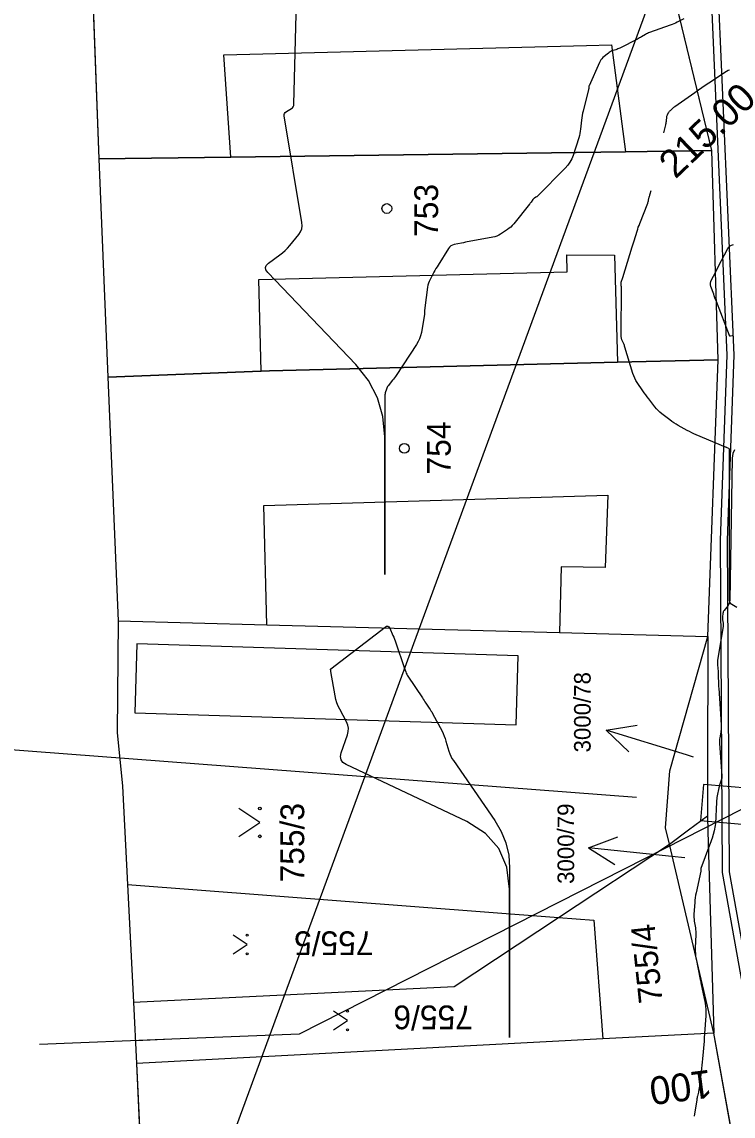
# Model space of a CAD drawing. Extents: x -534481 to -534262, y -1190577 to -1190138.
# Drawn here: x -534435.09 to -534409.62, y -1190436.66 to -1190397.49 of the extents above; entities that cross this region are included whole.
import ezdxf

# ---------------------------------------------------------------- set-up
doc = ezdxf.new("R2010")
doc.units = 0
for name, color, linetype in [('_přístup', 7, 'Continuous'), ('Definiční body', 7, 'Continuous'), ('Polygon budovy', 7, 'Continuous'), ('Polygon parcely', 7, 'Continuous'), ('Vrstva 17', 7, 'Continuous'), ('Vrstva 18', 7, 'Continuous'), ('Vrstva 19', 7, 'Continuous'), ('Vrstva 31', 7, 'Continuous'), ('Vrstva 35', 7, 'Continuous'), ('Vrstva 46', 7, 'Continuous'), ('Vrstva 47', 7, 'Continuous'), ('Vrstva 48', 7, 'Continuous'), ('Vrstva 56', 7, 'Continuous'), ('Značky bodu BP', 7, 'Continuous')]:
    doc.layers.add(name, color=color, linetype=linetype)

msp = doc.modelspace()

# ---------------------------------------------------------------- linework, layer by layer
at = {"layer": '_přístup'}
msp.add_line((-534442.17, -1190423.028), (-534413.082, -1190425.244), dxfattribs=at)
msp.add_lwpolyline([(-534417.39, -1190422.659), (-534417.312, -1190420.188), (-534430.965, -1190419.755), (-534431.043, -1190422.227)], close=True, dxfattribs=at)
at = {"layer": 'Definiční body'}
for p, q in [((-534410.38, -1190402.1), (-534412.44, -1190393.55)), ((-534432.64, -1190394.16), (-534432.33, -1190402.39)), ((-534410.16, -1190409.59), (-534410.38, -1190402.1)), ((-534432.33, -1190402.39), (-534432.01, -1190410.21)), ((-534410.53, -1190419.49), (-534410.16, -1190409.59)), ((-534432.01, -1190410.21), (-534431.64, -1190418.94)), ((-534415.87, -1190429.55), (-534411.9, -1190426.93)), ((-534410.31, -1190433.69), (-534411.9, -1190426.93)), ((-534431.3, -1190428.37), (-534415.87, -1190429.55)), ((-534431.3, -1190428.37), (-534431.09, -1190432.58)), ((-534431.09, -1190432.58), (-534430.98, -1190434.78)), ((-534414.28, -1190433.9), (-534430.98, -1190434.78)), ((-534410.31, -1190433.69), (-534414.28, -1190433.9)), ((-534407.58, -1190448.75), (-534410.31, -1190433.69)), ((-534430.98, -1190434.78), (-534430.23, -1190451.45))]:
    msp.add_line(p, q, dxfattribs=at)
for points in [[(-534432.33, -1190402.39), (-534427.61, -1190402.33), (-534413.47, -1190402.14), (-534410.38, -1190402.1)], [(-534432.01, -1190410.21), (-534426.52, -1190410), (-534426.22, -1190409.99), (-534413.76, -1190409.68), (-534410.16, -1190409.59)], [(-534431.64, -1190418.94), (-534431.68, -1190422.93), (-534431.48, -1190424.85), (-534431.3, -1190428.37)], [(-534431.64, -1190418.94), (-534426.32, -1190419.08), (-534415.84, -1190419.35), (-534410.53, -1190419.49)], [(-534411.9, -1190426.93), (-534412.04, -1190426.35), (-534411.88, -1190424.31), (-534410.53, -1190419.49)], [(-534410.53, -1190419.49), (-534410.54, -1190424.42), (-534410.54, -1190425.91)], [(-534411.9, -1190426.93), (-534411.22, -1190426.42), (-534410.54, -1190425.91)], [(-534410.54, -1190425.91), (-534410.52, -1190426.47), (-534410.31, -1190433.69)], [(-534431.09, -1190432.58), (-534419.61, -1190432.02), (-534415.87, -1190429.55)], [(-534415.87, -1190429.55), (-534414.61, -1190429.65), (-534414.28, -1190433.9)]]:
    msp.add_lwpolyline(points, dxfattribs=at)
at = {"layer": 'Polygon parcely'}
for points in [[(-534432.64, -1190394.16), (-534432.33, -1190402.39), (-534427.61, -1190402.33), (-534427.86, -1190398.67), (-534414.87, -1190398.34), (-534413.97, -1190398.32), (-534413.47, -1190402.14), (-534410.38, -1190402.1), (-534412.44, -1190393.55), (-534415.89, -1190393.7), (-534421.6, -1190393.94), (-534427.8, -1190394.2)], [(-534410.38, -1190402.1), (-534413.47, -1190402.14), (-534427.61, -1190402.33), (-534432.33, -1190402.39), (-534432.01, -1190410.21), (-534426.52, -1190410), (-534426.6, -1190406.71), (-534415.56, -1190406.44), (-534415.57, -1190405.83), (-534413.87, -1190405.85), (-534413.76, -1190409.68), (-534410.16, -1190409.59)], [(-534432.01, -1190410.21), (-534431.64, -1190418.94), (-534426.32, -1190419.08), (-534426.42, -1190414.81), (-534414.11, -1190414.44), (-534414.2, -1190417.03), (-534415.78, -1190417), (-534415.84, -1190419.35), (-534410.53, -1190419.49), (-534410.16, -1190409.59), (-534413.76, -1190409.68), (-534426.22, -1190409.99), (-534426.52, -1190410)], [(-534422.89, -1190441.14), (-534413.83, -1190440.6), (-534412.6, -1190449.51), (-534407.58, -1190448.75), (-534410.31, -1190433.69), (-534414.28, -1190433.9), (-534430.98, -1190434.78), (-534430.23, -1190451.45), (-534422.73, -1190450.69), (-534422.94, -1190447.02), (-534422.61, -1190447)]]:
    msp.add_lwpolyline(points, close=True, dxfattribs=at)
at = {"layer": 'Vrstva 18'}
for points in [[(-534411.381, -1190397.388), (-534411.622, -1190397.509), (-534411.683, -1190397.538), (-534411.745, -1190397.565), (-534411.807, -1190397.591), (-534411.871, -1190397.614), (-534412.61, -1190397.873), (-534412.648, -1190397.888), (-534412.686, -1190397.904), (-534412.722, -1190397.922), (-534412.757, -1190397.942), (-534412.898, -1190398.027), (-534412.933, -1190398.048), (-534412.968, -1190398.068), (-534413.004, -1190398.087), (-534413.04, -1190398.106), (-534413.676, -1190398.431), (-534413.71, -1190398.447), (-534413.744, -1190398.463), (-534413.779, -1190398.476), (-534413.815, -1190398.489), (-534413.958, -1190398.535), (-534413.993, -1190398.548), (-534414.026, -1190398.565), (-534414.057, -1190398.584), (-534414.087, -1190398.607), (-534414.279, -1190398.773), (-534414.318, -1190398.81), (-534414.352, -1190398.852), (-534414.382, -1190398.896), (-534414.406, -1190398.945), (-534414.776, -1190399.782), (-534414.78, -1190399.793), (-534414.783, -1190399.803), (-534414.785, -1190399.814), (-534414.786, -1190399.825), (-534414.789, -1190399.869), (-534414.79, -1190399.88), (-534414.791, -1190399.891), (-534414.793, -1190399.902), (-534414.795, -1190399.913), (-534414.993, -1190400.688), (-534415.012, -1190400.766), (-534415.028, -1190400.846), (-534415.04, -1190400.925), (-534415.05, -1190401.006), (-534415.082, -1190401.328), (-534415.092, -1190401.408), (-534415.107, -1190401.488), (-534415.125, -1190401.566), (-534415.148, -1190401.644), (-534415.349, -1190402.273), (-534415.398, -1190402.399), (-534415.46, -1190402.517), (-534415.537, -1190402.627), (-534415.627, -1190402.728), (-534416.627, -1190403.728), (-534416.639, -1190403.74), (-534416.652, -1190403.75), (-534416.665, -1190403.76), (-534416.679, -1190403.77), (-534416.736, -1190403.805), (-534416.75, -1190403.814), (-534416.763, -1190403.825), (-534416.774, -1190403.837), (-534416.785, -1190403.85), (-534416.854, -1190403.944), (-534416.869, -1190403.965), (-534416.884, -1190403.985), (-534416.899, -1190404.004), (-534416.915, -1190404.024), (-534417.476, -1190404.727), (-534417.525, -1190404.784), (-534417.578, -1190404.836), (-534417.635, -1190404.883), (-534417.695, -1190404.927), (-534417.946, -1190405.091), (-534418.01, -1190405.128), (-534418.077, -1190405.159), (-534418.147, -1190405.183), (-534418.219, -1190405.2), (-534419.069, -1190405.359), (-534419.136, -1190405.371), (-534419.204, -1190405.384), (-534419.271, -1190405.397), (-534419.339, -1190405.41), (-534419.608, -1190405.464), (-534419.672, -1190405.483), (-534419.728, -1190405.513), (-534419.775, -1190405.555), (-534419.816, -1190405.608), (-534420.184, -1190406.201), (-534420.222, -1190406.264), (-534420.259, -1190406.327), (-534420.296, -1190406.391), (-534420.331, -1190406.456), (-534420.47, -1190406.715), (-534420.502, -1190406.781), (-534420.527, -1190406.849), (-534420.546, -1190406.918), (-534420.559, -1190406.99), (-534420.657, -1190407.725), (-534420.659, -1190407.744), (-534420.661, -1190407.764), (-534420.663, -1190407.783), (-534420.664, -1190407.802), (-534420.667, -1190407.88), (-534420.668, -1190407.9), (-534420.67, -1190407.919), (-534420.672, -1190407.938), (-534420.675, -1190407.958), (-534420.783, -1190408.613), (-534420.808, -1190408.727), (-534420.845, -1190408.836), (-534420.892, -1190408.94), (-534420.951, -1190409.04), (-534421.684, -1190410.148), (-534421.714, -1190410.193), (-534421.745, -1190410.236), (-534421.778, -1190410.279), (-534421.811, -1190410.321), (-534421.971, -1190410.517), (-534421.991, -1190410.546), (-534422.009, -1190410.575), (-534422.024, -1190410.607), (-534422.035, -1190410.64), (-534422.075, -1190410.776), (-534422.083, -1190410.811), (-534422.089, -1190410.845), (-534422.093, -1190410.88), (-534422.094, -1190410.915), (-534422.094, -1190416.759), (-534422.094, -1190416.802), (-534422.094, -1190416.844), (-534422.093, -1190416.887), (-534422.092, -1190416.93), (-534422.088, -1190417.101), (-534422.087, -1190417.144), (-534422.086, -1190417.187), (-534422.086, -1190417.23), (-534422.085, -1190417.272), (-534422.086, -1190417.23), (-534422.086, -1190417.187), (-534422.087, -1190417.144), (-534422.088, -1190417.101), (-534422.092, -1190416.93), (-534422.093, -1190416.887), (-534422.094, -1190416.844), (-534422.094, -1190416.802), (-534422.094, -1190416.759), (-534422.094, -1190412.345), (-534422.159, -1190411.621), (-534422.354, -1190410.949), (-534422.678, -1190410.329), (-534423.131, -1190409.761), (-534426.285, -1190406.464), (-534426.349, -1190406.375), (-534426.365, -1190406.29), (-534426.334, -1190406.21), (-534426.256, -1190406.134), (-534425.85, -1190405.835), (-534425.752, -1190405.759), (-534425.659, -1190405.677), (-534425.572, -1190405.589), (-534425.49, -1190405.495), (-534425.174, -1190405.108), (-534425.107, -1190405.008), (-534425.066, -1190404.902), (-534425.049, -1190404.789), (-534425.057, -1190404.669), (-534425.691, -1190400.858), (-534425.692, -1190400.81), (-534425.681, -1190400.767), (-534425.656, -1190400.732), (-534425.617, -1190400.702), (-534425.437, -1190400.597), (-534425.397, -1190400.567), (-534425.368, -1190400.531), (-534425.351, -1190400.488), (-534425.344, -1190400.439), (-534425.133, -1190392.149)], [(-534409.609, -1190408.718), (-534409.623, -1190408.723), (-534409.638, -1190408.727), (-534409.653, -1190408.73), (-534409.713, -1190408.741), (-534409.727, -1190408.742), (-534409.738, -1190408.738), (-534409.747, -1190408.73), (-534409.754, -1190408.718), (-534410.219, -1190407.501), (-534410.244, -1190407.435), (-534410.268, -1190407.37), (-534410.292, -1190407.305), (-534410.315, -1190407.239), (-534410.411, -1190406.969), (-534410.426, -1190406.907), (-534410.429, -1190406.846), (-534410.418, -1190406.787), (-534410.394, -1190406.728), (-534410.24, -1190406.436), (-534410.149, -1190406.261), (-534409.807, -1190405.61), (-534409.771, -1190405.555), (-534409.725, -1190405.512), (-534409.671, -1190405.482), (-534409.608, -1190405.463)]]:
    msp.add_lwpolyline(points, dxfattribs=at)
msp.add_lwpolyline([(-534417.621, -1190427.776), (-534417.621, -1190433.845), (-534417.621, -1190428.541), (-534417.717, -1190427.753), (-534418.004, -1190427.087), (-534418.483, -1190426.543), (-534419.154, -1190426.12), (-534423.474, -1190424.08), (-534423.591, -1190424.003), (-534423.659, -1190423.907), (-534423.68, -1190423.791), (-534423.652, -1190423.654), (-534423.428, -1190423.016), (-534423.398, -1190422.896), (-534423.395, -1190422.779), (-534423.417, -1190422.664), (-534423.464, -1190422.55), (-534423.707, -1190422.101), (-534423.763, -1190421.987), (-534423.809, -1190421.87), (-534423.845, -1190421.749), (-534423.871, -1190421.625), (-534424.02, -1190420.753), (-534424.023, -1190420.735), (-534424.027, -1190420.717), (-534424.034, -1190420.68), (-534424.034, -1190420.672), (-534424.033, -1190420.664), (-534424.029, -1190420.657), (-534424.023, -1190420.651), (-534422.084, -1190419.159), (-534422.031, -1190419.13), (-534421.986, -1190419.127), (-534421.947, -1190419.151), (-534421.915, -1190419.202), (-534421.8, -1190419.46), (-534421.772, -1190419.524), (-534421.746, -1190419.59), (-534421.721, -1190419.655), (-534421.697, -1190419.722), (-534421.393, -1190420.603), (-534421.338, -1190420.764), (-534421.323, -1190420.804), (-534421.305, -1190420.842), (-534421.285, -1190420.879), (-534421.263, -1190420.915), (-534420.746, -1190421.695), (-534420.715, -1190421.741), (-534420.685, -1190421.786), (-534420.654, -1190421.832), (-534420.623, -1190421.877), (-534420.5, -1190422.059), (-534420.47, -1190422.104), (-534420.441, -1190422.151), (-534420.413, -1190422.198), (-534420.387, -1190422.246), (-534420.043, -1190422.888), (-534420, -1190422.972), (-534419.963, -1190423.059), (-534419.929, -1190423.147), (-534419.901, -1190423.237), (-534419.796, -1190423.601), (-534419.766, -1190423.691), (-534419.729, -1190423.777), (-534419.686, -1190423.86), (-534419.635, -1190423.939), (-534418.151, -1190426.079), (-534417.919, -1190426.472), (-534417.753, -1190426.886), (-534417.654, -1190427.32)], close=True, dxfattribs=at)
at = {"layer": 'Vrstva 19'}
for points in [[(-534412.097, -1190401.462), (-534412.031, -1190401.184), (-534412.024, -1190401.15), (-534412.018, -1190401.117), (-534412.012, -1190401.083), (-534412.008, -1190401.049), (-534411.99, -1190400.888), (-534411.987, -1190400.867), (-534411.981, -1190400.846), (-534411.973, -1190400.826), (-534411.963, -1190400.806), (-534411.918, -1190400.73), (-534411.906, -1190400.712), (-534411.893, -1190400.694), (-534411.879, -1190400.678), (-534411.863, -1190400.662), (-534411.781, -1190400.585), (-534411.762, -1190400.567), (-534411.742, -1190400.55), (-534411.721, -1190400.534), (-534411.7, -1190400.519), (-534410.987, -1190400.016), (-534410.864, -1190399.93), (-534410.741, -1190399.845), (-534410.617, -1190399.761), (-534410.492, -1190399.678), (-534409.853, -1190399.254), (-534409.797, -1190399.225), (-534409.746, -1190399.212)], [(-534409.49, -1190418.456), (-534409.659, -1190418.354), (-534409.696, -1190418.326), (-534409.722, -1190418.292), (-534409.738, -1190418.251), (-534409.743, -1190418.205), (-534409.743, -1190412.814), (-534409.745, -1190412.8), (-534409.75, -1190412.787), (-534409.759, -1190412.777), (-534409.772, -1190412.769), (-534409.83, -1190412.742), (-534409.845, -1190412.735), (-534409.86, -1190412.728), (-534409.874, -1190412.722), (-534409.889, -1190412.716), (-534410.937, -1190412.277), (-534411.021, -1190412.241), (-534411.103, -1190412.202), (-534411.185, -1190412.161), (-534411.265, -1190412.118), (-534411.586, -1190411.939), (-534411.664, -1190411.894), (-534411.739, -1190411.846), (-534411.813, -1190411.795), (-534411.885, -1190411.742), (-534412.17, -1190411.523), (-534412.239, -1190411.466), (-534412.304, -1190411.405), (-534412.365, -1190411.34), (-534412.421, -1190411.271), (-534412.641, -1190410.986), (-534412.695, -1190410.915), (-534412.748, -1190410.843), (-534412.8, -1190410.771), (-534412.851, -1190410.697), (-534413.053, -1190410.403), (-534413.101, -1190410.328), (-534413.142, -1190410.25), (-534413.177, -1190410.169), (-534413.206, -1190410.085), (-534413.494, -1190409.135), (-534413.504, -1190409.105), (-534413.514, -1190409.076), (-534413.525, -1190409.047), (-534413.537, -1190409.018), (-534413.601, -1190408.872), (-534413.606, -1190408.858), (-534413.61, -1190408.844), (-534413.613, -1190408.83), (-534413.616, -1190408.815), (-534413.623, -1190408.757), (-534413.624, -1190408.742), (-534413.625, -1190408.728), (-534413.626, -1190408.713), (-534413.626, -1190408.698), (-534413.621, -1190406.998), (-534413.621, -1190406.983), (-534413.621, -1190406.967), (-534413.622, -1190406.952), (-534413.623, -1190406.936), (-534413.629, -1190406.875), (-534413.63, -1190406.86), (-534413.629, -1190406.845), (-534413.627, -1190406.83), (-534413.623, -1190406.815), (-534413.571, -1190406.644), (-534413.23, -1190405.54), (-534413.166, -1190405.331), (-534413.058, -1190404.984), (-534413.036, -1190404.914), (-534413.013, -1190404.845), (-534412.988, -1190404.777), (-534412.962, -1190404.709), (-534412.678, -1190403.984), (-534412.668, -1190403.958), (-534412.659, -1190403.93), (-534412.651, -1190403.903), (-534412.644, -1190403.875), (-534412.619, -1190403.763), (-534412.612, -1190403.735), (-534412.605, -1190403.708), (-534412.597, -1190403.68), (-534412.589, -1190403.653), (-534412.552, -1190403.534)], [(-534409.564, -1190412.815), (-534409.631, -1190412.948), (-534409.655, -1190413.113), (-534409.741, -1190418.207), (-534409.746, -1190418.254), (-534409.757, -1190418.299), (-534409.776, -1190418.34), (-534409.802, -1190418.38), (-534409.943, -1190418.561), (-534409.96, -1190418.585), (-534409.972, -1190418.611), (-534409.981, -1190418.638), (-534409.986, -1190418.667), (-534409.998, -1190418.788), (-534410, -1190418.816), (-534410, -1190418.844), (-534409.999, -1190418.873), (-534409.995, -1190418.901), (-534409.977, -1190419.014), (-534409.974, -1190419.042), (-534409.973, -1190419.07), (-534409.974, -1190419.098), (-534409.978, -1190419.126), (-534410.172, -1190420.287), (-534410.179, -1190420.342), (-534410.183, -1190420.398), (-534410.183, -1190420.453), (-534410.18, -1190420.509), (-534410.159, -1190420.745), (-534410.155, -1190420.795), (-534410.152, -1190420.845), (-534410.15, -1190420.894), (-534410.149, -1190420.944), (-534410.145, -1190421.144), (-534410.143, -1190421.194), (-534410.142, -1190421.244), (-534410.139, -1190421.294), (-534410.136, -1190421.344), (-534410.057, -1190422.459), (-534410.055, -1190422.498), (-534410.053, -1190422.536), (-534410.051, -1190422.575), (-534410.05, -1190422.613), (-534410.047, -1190422.767), (-534410.047, -1190422.806), (-534410.049, -1190422.844), (-534410.053, -1190422.882), (-534410.059, -1190422.92), (-534410.097, -1190423.123), (-534410.104, -1190423.169), (-534410.108, -1190423.216), (-534410.11, -1190423.263), (-534410.108, -1190423.31), (-534410.022, -1190424.498), (-534410.021, -1190424.534), (-534410.024, -1190424.57), (-534410.031, -1190424.605), (-534410.042, -1190424.639), (-534410.091, -1190424.776), (-534410.103, -1190424.81), (-534410.113, -1190424.845), (-534410.123, -1190424.88), (-534410.13, -1190424.916), (-534410.186, -1190425.194), (-534410.197, -1190425.253), (-534410.205, -1190425.311), (-534410.211, -1190425.37), (-534410.216, -1190425.429), (-534410.255, -1190426.19), (-534410.261, -1190426.257), (-534410.27, -1190426.324), (-534410.283, -1190426.39), (-534410.3, -1190426.455), (-534410.375, -1190426.715), (-534410.395, -1190426.779), (-534410.416, -1190426.844), (-534410.437, -1190426.908), (-534410.46, -1190426.971), (-534410.769, -1190427.798), (-534410.772, -1190427.806), (-534410.773, -1190427.813), (-534410.774, -1190427.821), (-534410.775, -1190427.829), (-534410.775, -1190427.86), (-534410.775, -1190427.868), (-534410.776, -1190427.876), (-534410.777, -1190427.884), (-534410.778, -1190427.892), (-534410.944, -1190428.67), (-534410.961, -1190428.757), (-534410.975, -1190428.845), (-534410.986, -1190428.934), (-534410.994, -1190429.023), (-534411.022, -1190429.432), (-534411.024, -1190429.495), (-534411.023, -1190429.557), (-534411.019, -1190429.619), (-534411.01, -1190429.68), (-534410.969, -1190429.927), (-534410.96, -1190429.988), (-534410.955, -1190430.05), (-534410.953, -1190430.112), (-534410.954, -1190430.175), (-534410.975, -1190430.646), (-534410.976, -1190430.745), (-534410.971, -1190430.844), (-534410.961, -1190430.942), (-534410.944, -1190431.039), (-534410.797, -1190431.775), (-534410.79, -1190431.806), (-534410.779, -1190431.868), (-534410.774, -1190431.888), (-534410.772, -1190431.899), (-534410.624, -1190432.622), (-534410.605, -1190432.733), (-534410.594, -1190432.845), (-534410.591, -1190432.958), (-534410.596, -1190433.071), (-534410.645, -1190433.704), (-534410.647, -1190433.728), (-534410.648, -1190433.751), (-534410.649, -1190433.774), (-534410.65, -1190433.797), (-534410.652, -1190433.889), (-534410.652, -1190433.912), (-534410.653, -1190433.935), (-534410.655, -1190433.958), (-534410.657, -1190433.981), (-534410.714, -1190434.619), (-534410.724, -1190434.732), (-534410.736, -1190434.844), (-534410.748, -1190434.957), (-534410.762, -1190435.069), (-534410.837, -1190435.673), (-534410.842, -1190435.708), (-534410.847, -1190435.742), (-534410.854, -1190435.776), (-534410.862, -1190435.81), (-534410.895, -1190435.945), (-534410.903, -1190435.979), (-534410.91, -1190436.013), (-534410.916, -1190436.047), (-534410.922, -1190436.082), (-534411.012, -1190436.668)]]:
    msp.add_lwpolyline(points, dxfattribs=at)
at = {"layer": 'Vrstva 31'}
msp.add_lwpolyline([(-534405.695, -1190512.351), (-534434.703, -1190456.89), (-534411.68, -1190394.248)], dxfattribs=at)
at = {"layer": 'Vrstva 35'}
for points in [[(-534405.407, -1190514.348), (-534394.258, -1190501.982), (-534392.12, -1190496.869), (-534393.492, -1190488.211), (-534397.35, -1190478.035), (-534403.219, -1190464.54), (-534405.491, -1190456.905), (-534409.051, -1190433.21), (-534409.998, -1190427.948), (-534410.066, -1190416.042), (-534409.827, -1190409.421), (-534410.645, -1190390.84)], [(-534405.057, -1190514.333), (-534394.044, -1190502.118), (-534391.862, -1190496.9), (-534393.249, -1190488.146), (-534397.118, -1190477.94), (-534402.983, -1190464.455), (-534405.247, -1190456.85), (-534408.804, -1190433.17), (-534409.748, -1190427.925), (-534409.816, -1190416.046), (-534409.577, -1190409.42), (-534410.397, -1190390.795)]]:
    msp.add_lwpolyline(points, dxfattribs=at)
at = {"layer": 'Vrstva 46'}
for centre in [(-534422.017, -1190404.175), (-534421.394, -1190412.762)]:
    msp.add_circle(centre, 0.175, dxfattribs=at)
at = {"layer": 'Vrstva 47'}
for p, q in [((-534414.16, -1190422.853), (-534413.056, -1190422.667)), ((-534411.29, -1190423.73), (-534414.16, -1190422.853)), ((-534414.16, -1190422.853), (-534413.349, -1190423.624)), ((-534411.04, -1190423.81), (-534411.29, -1190423.73)), ((-534414.795, -1190427.056), (-534413.746, -1190426.663)), ((-534411.81, -1190427.37), (-534414.795, -1190427.056)), ((-534414.795, -1190427.056), (-534413.851, -1190427.659)), ((-534411.35, -1190427.42), (-534411.81, -1190427.37))]:
    msp.add_line(p, q, dxfattribs=at)
at = {"layer": 'Vrstva 48'}
for points in [[(-534427.317, -1190426.649), (-534426.567, -1190426.149), (-534427.317, -1190425.649)], [(-534427.523, -1190430.857), (-534427.02, -1190430.522), (-534427.523, -1190430.187)], [(-534423.932, -1190433.576), (-534423.429, -1190433.241), (-534423.932, -1190432.906)]]:
    msp.add_lwpolyline(points, dxfattribs=at)
for centre, radius in [((-534426.567, -1190425.649), 0.05), ((-534426.567, -1190426.649), 0.05), ((-534427.02, -1190430.187), 0.0335), ((-534427.02, -1190430.857), 0.0335), ((-534423.429, -1190432.906), 0.0335), ((-534423.429, -1190433.576), 0.0335)]:
    msp.add_circle(centre, radius, dxfattribs=at)
at = {"layer": 'Vrstva 56'}
for points in [[(-534388.755, -1190426.81), (-534407.258, -1190424.643), (-534412.763, -1190427.438), (-534425.162, -1190433.733), (-534429.719, -1190433.916), (-534434.452, -1190434.105)], [(-534388.755, -1190426.81), (-534407.258, -1190424.643), (-534412.763, -1190427.438), (-534425.162, -1190433.733), (-534429.719, -1190433.916), (-534431.021, -1190433.968)], [(-534388.755, -1190426.81), (-534407.258, -1190424.643), (-534412.763, -1190427.438), (-534425.162, -1190433.733), (-534429.719, -1190433.916), (-534431.021, -1190433.968)]]:
    msp.add_lwpolyline(points, dxfattribs=at)
at = {"layer": 'Značky bodu BP'}
msp.add_lwpolyline([(-534407.407, -1190426.376), (-534407.295, -1190425.083), (-534410.68, -1190424.789), (-534410.792, -1190426.083)], close=True, dxfattribs=at)

# ---------------------------------------------------------------- texts
at = {"layer": 'Polygon budovy'}
for s, height, rotation, p in [('753', 0.85, 90, (-534420.183, -1190405.191)), ('754', 0.85, 90, (-534419.731, -1190413.696)), ('3000/78', 0.595, 90, (-534414.72, -1190423.645)), ('755/3', 0.85, 90, (-534424.977, -1190428.3)), ('3000/79', 0.595, 90, (-534415.312, -1190428.351)), ('755/5', 0.85, 180, (-534422.495, -1190430.05)), ('755/4', 0.85, 96, (-534412.14, -1190432.582)), ('755/6', 0.85, 180, (-534418.938, -1190432.705))]:
    msp.add_text(s, height=height, rotation=rotation, dxfattribs=at).set_placement(p)
at = {"layer": 'Vrstva 17'}
msp.add_text('215.00', height=1, rotation=43.7488, dxfattribs=at).set_placement((-534411.684, -1190403.143))
at = {"layer": 'Vrstva 31'}
msp.add_text('100', height=1, rotation=187.318, dxfattribs=at).set_placement((-534410.45, -1190434.999))

doc.saveas('drawing.dxf')
